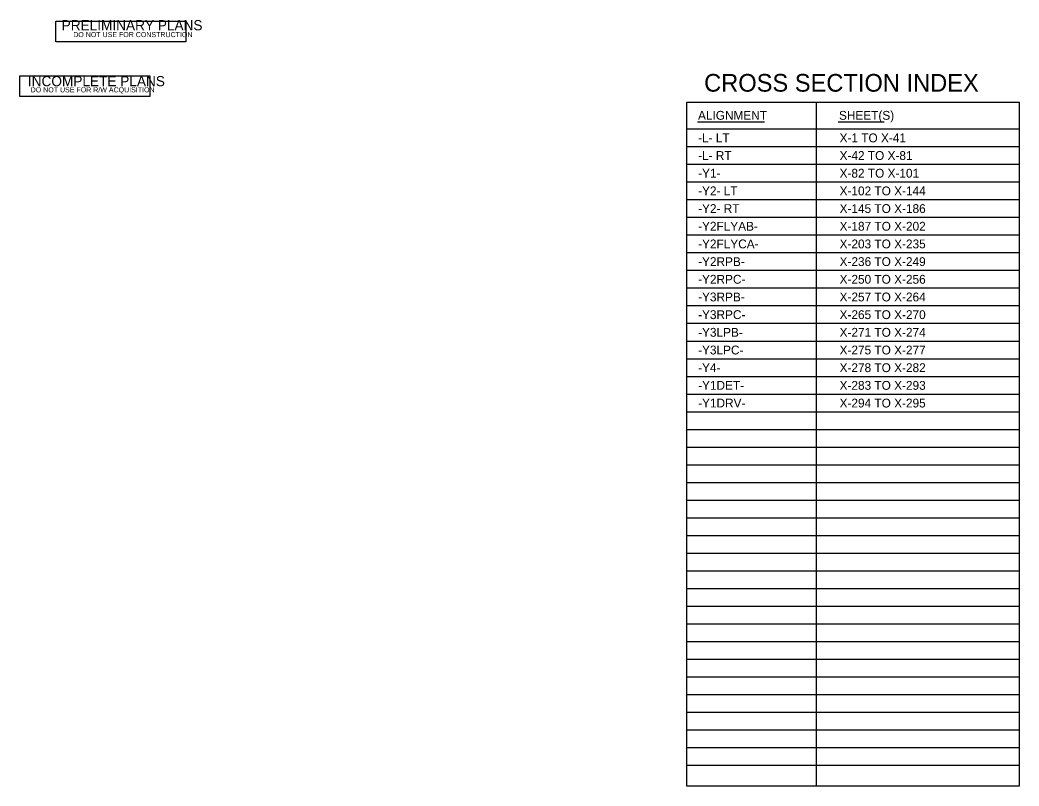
# Model space of a CAD drawing. Extents: x -1147 to 1810, y 2549 to 4545.
# Drawn here: x 680 to 1810, y 2891 to 3758 of the extents above; entities that cross this region are included whole.
import ezdxf

# ---------------------------------------------------------------- set-up
doc = ezdxf.new("R2010")
doc.units = 0
for name, color, linetype in [('Sheet Plan CELL', 7, 'Continuous'), ('Sheet Sticker Incomplete CELL', 7, 'Continuous'), ('Sheet Sticker Preliminary CELL', 7, 'Continuous')]:
    doc.layers.add(name, color=color, linetype=linetype)

msp = doc.modelspace()

# ---------------------------------------------------------------- linework, layer by layer
at = {"layer": 'Sheet Plan CELL'}
for p, q in [((1580.7, 3664.9), (1580.7, 2891.3)), ((1446.7, 3642.8), (1522.3, 3642.8)), ((1605.7, 3642.8), (1657.7, 3642.8)), ((1434.3, 3634.8), (1810.1, 3634.8)), ((1434.3, 3614.8), (1810.1, 3614.8)), ((1434.3, 3594.8), (1810.1, 3594.8)), ((1434.3, 3574.8), (1810.1, 3574.8)), ((1434.3, 3554.8), (1810.1, 3554.8)), ((1434.3, 3534.8), (1810.1, 3534.8)), ((1434.3, 3514.8), (1810.1, 3514.8)), ((1434.3, 3494.8), (1810.1, 3494.8)), ((1434.3, 3474.8), (1810.1, 3474.8)), ((1434.3, 3454.8), (1810.1, 3454.8)), ((1434.3, 3434.8), (1810.1, 3434.8)), ((1434.3, 3414.8), (1810.1, 3414.8)), ((1434.3, 3394.8), (1810.1, 3394.8)), ((1434.3, 3374.8), (1810.1, 3374.8)), ((1434.3, 3354.8), (1810.1, 3354.8)), ((1434.3, 3334.8), (1810.1, 3334.8)), ((1434.3, 3314.8), (1810.1, 3314.8)), ((1434.3, 3294.8), (1810.1, 3294.8)), ((1434.3, 3274.8), (1810.1, 3274.8)), ((1434.3, 3254.8), (1810.1, 3254.8)), ((1434.3, 3234.8), (1810.1, 3234.8)), ((1434.3, 3214.8), (1810.1, 3214.8)), ((1434.3, 3194.8), (1810.1, 3194.8)), ((1434.3, 3174.8), (1810.1, 3174.8)), ((1434.3, 3154.8), (1810.1, 3154.8)), ((1434.3, 3134.8), (1810.1, 3134.8)), ((1434.3, 3114.8), (1810.1, 3114.8)), ((1434.3, 3094.8), (1810.1, 3094.8)), ((1434.3, 3074.8), (1810.1, 3074.8)), ((1434.3, 3054.8), (1810.1, 3054.8)), ((1434.3, 3034.8), (1810.1, 3034.8)), ((1434.3, 3014.8), (1810.1, 3014.8)), ((1434.3, 2994.8), (1810.1, 2994.8)), ((1434.3, 2974.8), (1810.1, 2974.8)), ((1434.3, 2954.8), (1810.1, 2954.8)), ((1434.3, 2934.8), (1810.1, 2934.8)), ((1434.3, 2914.8), (1810.1, 2914.8))]:
    msp.add_line(p, q, dxfattribs=at)
msp.add_lwpolyline([(1434.3, 3664.9), (1810.1, 3664.9), (1810.1, 2891.3), (1434.3, 2891.3)], close=True, dxfattribs=at)
at = {"layer": 'Sheet Sticker Incomplete CELL'}
msp.add_lwpolyline([(680.3, 3671.3), (680.3, 3694.8), (827.3, 3694.8), (827.3, 3671.3)], close=True, dxfattribs=at)
at = {"layer": 'Sheet Sticker Preliminary CELL'}
msp.add_lwpolyline([(721, 3733.2), (721, 3756.7), (868, 3756.7), (868, 3733.2)], close=True, dxfattribs=at)

# ---------------------------------------------------------------- texts
at = {"layer": 'Sheet Plan CELL'}
for s, height, p in [('CROSS SECTION INDEX', 20, (1454, 3676.9)), ('ALIGNMENT', 10, (1447.1, 3645.1)), ('SHEET(S)', 10, (1606.5, 3645.1)), ('-L- LT', 10, (1447.2, 3619.6)), ('X-1 TO X-41', 10, (1607.2, 3619.6)), ('-L- RT', 10, (1447.2, 3599.6)), ('X-42 TO X-81', 10, (1607.2, 3599.6)), ('-Y1-', 10, (1447.2, 3579.6)), ('X-82 TO X-101', 10, (1607.2, 3579.6)), ('-Y2- LT', 10, (1447.2, 3559.6)), ('X-102 TO X-144', 10, (1607.2, 3559.6)), ('-Y2- RT', 10, (1447.2, 3539.6)), ('X-145 TO X-186', 10, (1607.2, 3539.6)), ('-Y2FLYAB-', 10, (1447.2, 3519.6)), ('X-187 TO X-202', 10, (1607.2, 3519.6)), ('-Y2FLYCA-', 10, (1447.2, 3499.6)), ('X-203 TO X-235', 10, (1607.2, 3499.6)), ('-Y2RPB-', 10, (1447.2, 3479.6)), ('X-236 TO X-249', 10, (1607.2, 3479.6)), ('-Y2RPC-', 10, (1447.2, 3459.6)), ('X-250 TO X-256', 10, (1607.2, 3459.6)), ('-Y3RPB-', 10, (1447.2, 3439.6)), ('X-257 TO X-264', 10, (1607.2, 3439.6)), ('-Y3RPC-', 10, (1447.2, 3419.6)), ('X-265 TO X-270', 10, (1607.2, 3419.6)), ('-Y3LPB-', 10, (1447.2, 3399.6)), ('X-271 TO X-274', 10, (1607.2, 3399.6)), ('-Y3LPC-', 10, (1447.2, 3379.6)), ('X-275 TO X-277', 10, (1607.2, 3379.6)), ('-Y4-', 10, (1447.2, 3359.6)), ('X-278 TO X-282', 10, (1607.2, 3359.6)), ('-Y1DET-', 10, (1447.2, 3339.6)), ('X-283 TO X-293', 10, (1607.2, 3339.6)), ('-Y1DRV-', 10, (1447.2, 3319.6)), ('X-294 TO X-295', 10, (1607.2, 3319.6))]:
    msp.add_text(s, height=height, rotation=0, dxfattribs=at).set_placement(p)
at = {"layer": 'Sheet Sticker Incomplete CELL'}
for s, height, p in [('INCOMPLETE PLANS', 11.52, (689.3, 3683)), ('DO NOT USE FOR R/W ACQUISITION', 5.76, (692.5, 3676.1))]:
    msp.add_text(s, height=height, dxfattribs=at).set_placement(p)
at = {"layer": 'Sheet Sticker Preliminary CELL'}
for s, height, p in [('PRELIMINARY PLANS', 11.52, (727.5, 3746.3)), ('DO NOT USE FOR CONSTRUCTION', 5.76, (740.6, 3738.6))]:
    msp.add_text(s, height=height, dxfattribs=at).set_placement(p)

doc.saveas('drawing.dxf')
